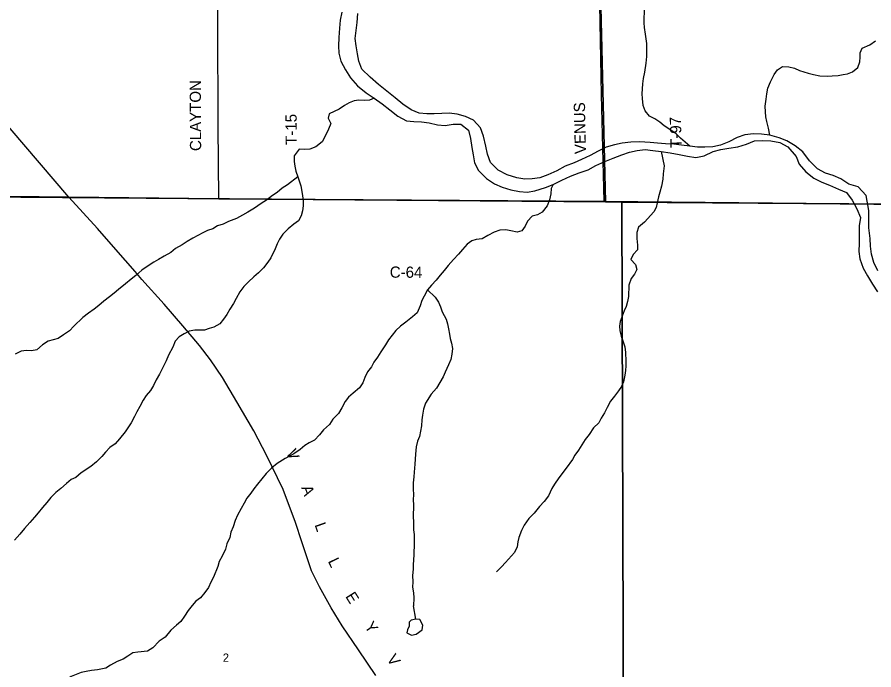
# Model space of a CAD drawing. Extents: x 1312308 to 1684953, y 460642 to 865172.
# Drawn here: x 1433853 to 1439573, y 606234 to 610594 of the extents above; entities that cross this region are included whole.
import ezdxf

# ---------------------------------------------------------------- set-up
doc = ezdxf.new("R2010")
doc.units = 0
for name, color, linetype in [('GM_X_County_Road', 7, 'Continuous'), ('GM_X_County_Road_Text', 7, 'Continuous'), ('GM_X_Minor_Lake', 7, 'Continuous'), ('GM_X_Minor_River', 7, 'Continuous'), ('GM_X_Section', 7, 'Continuous'), ('GM_X_Section_Text', 7, 'Continuous'), ('GM_X_Township', 7, 'Continuous'), ('GM_X_Township_Road', 7, 'Continuous'), ('GM_X_Township_Road_Text', 7, 'Continuous')]:
    doc.layers.add(name, color=color, linetype=linetype)

msp = doc.modelspace()

# ---------------------------------------------------------------- linework, layer by layer
at = {"layer": 'GM_X_County_Road'}
for points in [[(1434197.2, 609392.5), (1433321.1, 610416.1), (1432855.2, 610960.9), (1432519.8, 611370.7), (1432273.9, 611680.1), (1431928.4, 612099), (1431461.6, 612653.5), (1431109.8, 613075.1), (1430537.7, 613750.3), (1429745.8, 614732.5), (1429325.1, 615284.2), (1429124.3, 615518.8), (1428892, 615774.3), (1428690.9, 615972.9), (1428138.6, 616505.8), (1427967.9, 616667.8), (1427961, 616674.7)], [(1427248.1, 609464.9), (1427248.1, 609464.9), (1430057.8, 609437.8), (1434197.2, 609392.5)], [(1434197.2, 609392.5), (1435199.7, 609380.4), (1437771.4, 609361.5), (1440472, 609335.1), (1443062.5, 609310)], [(1436246.7, 606197), (1436132.6, 606368.7), (1436023, 606528.6), (1435948.4, 606647.6), (1435871.8, 606787.7), (1435819.1, 606895.2), (1435756.4, 607081.9), (1435709.1, 607224.4), (1435651.4, 607379.2), (1435629.5, 607438.2), (1435591.3, 607516.9), (1435519.6, 607663.1), (1435432.6, 607831.6), (1435319.8, 608023.6), (1435223.8, 608185.9), (1435144.7, 608305), (1435070.1, 608401.4), (1434958.9, 608532), (1434835.3, 608676.1), (1434685.7, 608841.3), (1434641.3, 608895.3), (1434511.5, 609042), (1434389.2, 609181.2), (1434197.2, 609392.5)]]:
    msp.add_lwpolyline(points, dxfattribs=at)
at = {"layer": 'GM_X_Minor_Lake'}
for points in [[(1436541.6, 606570.1), (1436515.6, 606572.6), (1436483.4, 606565.3), (1436471.1, 606553.6), (1436470.5, 606525.5), (1436458, 606501.8), (1436455.6, 606481.8), (1436485.3, 606465.1), (1436517.5, 606472.4)], [(1436517.5, 606472.4), (1436556.2, 606501.7), (1436560.9, 606533.6), (1436541.6, 606570.1)]]:
    msp.add_lwpolyline(points, dxfattribs=at)
at = {"layer": 'GM_X_Minor_River'}
for points in [[(1438343.3, 609732.7), (1438281.9, 609786.6), (1438252.4, 609815.3), (1438216.8, 609840), (1438173.2, 609866.9), (1438143.6, 609891.5), (1438110, 609914.2), (1438074.3, 609932.9), (1438046.9, 609967.5), (1438031.6, 610003.9), (1438028.6, 610050.1), (1438025.2, 610082.3), (1438030.6, 610148.4), (1438035.3, 610184.4), (1438044.2, 610226.4), (1438051.5, 610286.4), (1438056.4, 610330.5), (1438057.2, 610372.6), (1438056.1, 610416.8), (1438047.4, 610479.1), (1438042.3, 610525.3), (1438038.9, 610555.5), (1438041, 610657.8)], [(1436020.1, 610626.5), (1436008.9, 610572.6), (1436005.9, 610520.6), (1436000.6, 610458.6), (1435999.4, 610402.5), (1436000.4, 610352.4), (1436013.3, 610300), (1436044.2, 610241.2), (1436079.2, 610188.4), (1436126.2, 610135.3), (1436183.4, 610088), (1436236.8, 610052.7), (1436290.1, 610015.5), (1436341.4, 609974.3), (1436394.7, 609933.1), (1436452.2, 609901.8), (1436502.2, 609896.7), (1436552.3, 609893.6), (1436604.3, 609888.5), (1436660.1, 609875.3), (1436710.1, 609870.2), (1436764.5, 609879), (1436814.6, 609877.9), (1436865.9, 609838.8), (1436878.7, 609782.4), (1436887.6, 609724.1), (1436896.5, 609673.8), (1436905.5, 609621.5), (1436932.5, 609568.8), (1436985.5, 609515.6), (1437038.9, 609480.4), (1437090.5, 609457.2), (1437148.3, 609439.9), (1437206.2, 609428.7), (1437258.3, 609425.5), (1437308.6, 609434.5), (1437381.3, 609456.9), (1437431.8, 609475.9), (1437488.5, 609504.7), (1437547.2, 609531.5), (1437605.8, 609554.3), (1437664.4, 609575), (1437717.1, 609601.9), (1437775.8, 609630.7), (1437832.4, 609651.5), (1437891, 609674.3), (1437941.5, 609691.3), (1437991.8, 609702.2), (1438046.1, 609709), (1438096.1, 609703.9), (1438152.1, 609696.7), (1438212, 609687.4), (1438273.9, 609676), (1438327.8, 609664.9), (1438383.8, 609655.6), (1438440.2, 609668.4), (1438498.9, 609697.2), (1438551.3, 609710.1), (1438605.6, 609719), (1438664, 609727.7), (1438722.5, 609744.5), (1438775.1, 609767.4), (1438829.2, 609770.2), (1438885.3, 609767), (1438945.2, 609755.7), (1438998.8, 609726.5), (1439053.6, 609663.2), (1439074.6, 609612.7), (1439117.6, 609561.6), (1439172.9, 609518.4), (1439224.4, 609491.2), (1439276.2, 609472), (1439335.8, 609444.7), (1439389.5, 609423.5), (1439428.5, 609370.6), (1439459.3, 609313.8), (1439484.2, 609255.2)], [(1439540.1, 609241.9), (1439539.3, 609302.1), (1439521.3, 609402.6), (1439468.4, 609459.9), (1439406.6, 609477.2), (1439353.2, 609514.5), (1439301.5, 609535.6), (1439249.8, 609552.8), (1439196.2, 609580), (1439143.2, 609635.2), (1439098.3, 609694.3), (1439047, 609733.5), (1438991.6, 609766.7), (1438939.9, 609787.9), (1438878.1, 609805.2), (1438822.1, 609812.4), (1438770, 609813.6), (1438711.7, 609806.8), (1438661.2, 609789.9), (1438604.5, 609761.1), (1438547.9, 609738.2), (1438497.6, 609727.3), (1438445.4, 609724.4), (1438395.3, 609725.5), (1438343.3, 609732.7), (1438289.3, 609739.8), (1438237.3, 609745), (1438181.2, 609748.2), (1438129.1, 609751.3), (1438079.1, 609756.4), (1438007.1, 609762), (1437950.9, 609759.2), (1437892.6, 609752.4), (1437840.2, 609741.5), (1437785.8, 609724.7), (1437731.1, 609697.8), (1437678.4, 609668.9), (1437621.7, 609644.1), (1437571.1, 609621.1), (1437512.5, 609598.4), (1437455.7, 609567.5), (1437397, 609540.8), (1437342.5, 609519.9), (1437292.2, 609513), (1437242.1, 609512), (1437188.1, 609521.2), (1437124.4, 609540.6), (1437064.9, 609572), (1437013.8, 609623.2), (1436992.9, 609679.7), (1436982, 609732.1), (1436967.3, 609798.5), (1436946.4, 609855), (1436899.3, 609906.2), (1436845.7, 609929.3), (1436789.9, 609946.6), (1436737.9, 609951.7), (1436687.8, 609950.8), (1436637.6, 609947.9), (1436587.4, 609947), (1436537.4, 609952.1), (1436483.8, 609975.3), (1436428.4, 610012.5), (1436377.2, 610055.7), (1436321.9, 610099), (1436264.7, 610144.3), (1436209.6, 610193.6), (1436154.6, 610246.9), (1436133.6, 610299.4), (1436124.6, 610349.7), (1436115.7, 610402), (1436110.7, 610452.2), (1436115.8, 610504.2), (1436122.9, 610558.1), (1436128.2, 610618.1)], [(1438878.1, 609805.2), (1438868.9, 609852), (1438857.8, 609896.4), (1438852.4, 609928.6), (1438849.1, 609960.7), (1438847.9, 609998.9), (1438852.9, 610046.9), (1438857.6, 610080.9), (1438864.4, 610118.9), (1438883.3, 610162.7), (1438906.4, 610210.5), (1438929.1, 610242.1), (1438963.6, 610263.6), (1439005.7, 610262.8), (1439043.6, 610252.1), (1439077.4, 610237.4), (1439133.2, 610220.3), (1439169.1, 610211.6), (1439211.1, 610202.8), (1439263.2, 610199.9), (1439295.3, 610201.3), (1439333.5, 610204.6), (1439367.7, 610210), (1439397.9, 610215.4), (1439430.2, 610228.9), (1439466.9, 610258.3), (1439479.8, 610296.2), (1439482.4, 610326.2), (1439481, 610356.3), (1439495.6, 610386.2), (1439546.3, 610409.3), (1439584.9, 610436.7)], [(1436236.8, 610052.7), (1436205.1, 610039.7), (1436168.9, 610036.3), (1436134.9, 610039), (1436102.7, 610035.5), (1436070.4, 610022.1), (1436037.9, 610002.6), (1436003.3, 609979.2), (1435968.9, 609963.8), (1435936.5, 609948.3), (1435929.8, 609918.4), (1435947.2, 609883.9), (1435932.4, 609846.1), (1435907.2, 609794.4), (1435888.5, 609760.6), (1435847.7, 609727.3), (1435807.3, 609712), (1435773.1, 609710.6), (1435735.1, 609711.3), (1435702.1, 609667.8), (1435701.3, 609629.7), (1435706.7, 609599.5), (1435714, 609565.2), (1435727.3, 609526.9), (1435746.1, 609466.3), (1435753.4, 609430.1), (1435758.8, 609399.9), (1435762.2, 609369.7), (1435763.4, 609333.6), (1435758.7, 609299.6), (1435748, 609265.7), (1435731.3, 609233.9), (1435700.7, 609210.4), (1435662, 609181), (1435627.1, 609143.5), (1435604.4, 609109.8), (1435589.7, 609080), (1435575, 609046.2), (1435545.7, 608986.5), (1435527, 608956.8), (1435498.2, 608919.2), (1435463.4, 608885.8), (1435432.8, 608858.2), (1435398, 608824.8), (1435367.3, 608795.2), (1435340.5, 608759.6), (1435315.5, 608713.9), (1435296.7, 608680.2), (1435271.9, 608642.5), (1435253.1, 608608.8), (1435230.4, 608577.1), (1435205.7, 608545.4), (1435165.2, 608524.1), (1435134.9, 608514.7), (1435102.6, 608503.2), (1435072.5, 608503.8), (1435038.4, 608502.4), (1435002.1, 608497), (1434967.6, 608477.6), (1434935.2, 608458.2), (1434908.5, 608428.6), (1434891.6, 608388.7), (1434864.4, 608335.1), (1434847.7, 608299.3), (1434828.8, 608257.5), (1434803.7, 608209.8), (1434780.9, 608172.1), (1434762.1, 608134.3), (1434743.3, 608100.6), (1434714.5, 608067), (1434693.8, 608035.3), (1434670.9, 607993.6), (1434652.1, 607957.8), (1434637.4, 607926), (1434614.5, 607884.3), (1434573.2, 607824.9), (1434536.1, 607777.4), (1434507.3, 607743.8), (1434470.8, 607720.4), (1434442, 607688.9), (1434417.4, 607659.2), (1434382.5, 607623.8), (1434343.8, 607592.4), (1434280.7, 607549.4), (1434244, 607520), (1434213.7, 607506.5), (1434183, 607479), (1434144.2, 607445.6), (1434111.6, 607418.1), (1434076.8, 607384.7), (1434052, 607351), (1434021.2, 607317.5), (1433992.5, 607283.9), (1433967.8, 607254.3), (1433937, 607218.8), (1433902.1, 607179.3), (1433871.2, 607139.7), (1433834.3, 607100.3)], [(1438152.1, 609696.7), (1438171.8, 609600.1), (1438166.7, 609548), (1438164, 609511.9), (1438155, 609464), (1438144.1, 609424), (1438135.5, 609394.1), (1438126.6, 609354.2), (1438120, 609322.2), (1438103.3, 609292.4), (1438041.7, 609225.3), (1438000.9, 609190), (1437990.2, 609156), (1437989.4, 609115.9), (1437994.4, 609069.7), (1437995.8, 609039.6), (1437965.1, 609008.1), (1437950.4, 608974.2), (1437981.8, 608941.5), (1437991.1, 608907.3), (1437974.5, 608877.5), (1437951.8, 608847.8), (1437936.8, 608803.9), (1437935.3, 608727.7), (1437928.6, 608693.8), (1437919.9, 608661.8), (1437905.2, 608632), (1437892.5, 608596.1), (1437879.7, 608560.2), (1437875.1, 608530.2), (1437876.5, 608500.1), (1437885.7, 608463.8), (1437899, 608425.5), (1437910.3, 608391.2), (1437913.6, 608353), (1437916.4, 608296.8), (1437917.8, 608264.6), (1437915.1, 608232.6), (1437910.5, 608202.6), (1437901.6, 608158.6), (1437886.9, 608126.8), (1437868.2, 608097), (1437841.4, 608061.4), (1437814.6, 608027.8), (1437791.7, 607986.1), (1437774.9, 607950.3), (1437752.1, 607914.6), (1437735.5, 607884.8), (1437700.7, 607851.4), (1437671.7, 607805.8), (1437644.9, 607772.2), (1437624.1, 607736.4), (1437601.4, 607700.7), (1437576.6, 607669.1), (1437560, 607639.3), (1437518.7, 607581.9), (1437469.2, 607516.6), (1437440.3, 607475), (1437423.6, 607445.2), (1437400.6, 607397.5), (1437371.7, 607357.9), (1437340.9, 607324.4), (1437303.9, 607280.9), (1437269.1, 607245.5), (1437238.1, 607199.9), (1437221.3, 607164.1), (1437202.3, 607118.3), (1437195.7, 607088.3), (1437191, 607056.3), (1437174.2, 607018.5), (1437112.6, 606951.5), (1437086, 606921.9), (1437053.2, 606888.4)], [(1435727.3, 609526.9), (1435658, 609474), (1435621.4, 609450.6), (1435588.7, 609423.1), (1435558.2, 609401.6), (1435517.5, 609372.3), (1435482.9, 609348.8), (1435438.2, 609317.5), (1435393.5, 609290.3), (1435357, 609270.9), (1435318.4, 609249.5), (1435263.8, 609228.5), (1435227.4, 609211.1), (1435191, 609199.7), (1435158.5, 609180.3), (1435124.2, 609168.9), (1435091.8, 609153.4), (1435059.4, 609136), (1435024.9, 609116.5), (1434988.3, 609095.2), (1434953.8, 609073.7), (1434909.1, 609048.5), (1434878.5, 609022.9), (1434833.9, 608997.7), (1434797.3, 608974.3), (1434764.9, 608956.8), (1434728.3, 608933.4), (1434685.6, 608904.1), (1434644.7, 608868.8), (1434614.1, 608843.3), (1434575.3, 608811.9), (1434530.5, 608774.6), (1434499.9, 608751.1), (1434469.3, 608725.6), (1434432.6, 608696.2), (1434397.9, 608668.7), (1434367.3, 608643.2), (1434328.6, 608615.8), (1434292, 608588.4), (1434230.6, 608529.4), (1434201.9, 608497.8), (1434163.2, 608472.4), (1434126.6, 608447), (1434092.3, 608437.6), (1434060.1, 608430.2), (1434021.4, 608404.8), (1433984.7, 608371.4), (1433948.5, 608366.1), (1433914.4, 608366.7), (1433880.2, 608363.3), (1433839.6, 608342)], [(1437431.8, 609475.9), (1437418.5, 609449.5), (1437415.8, 609413.4), (1437407, 609373.4), (1437392.1, 609333.6), (1437359.2, 609292.1), (1437326.7, 609272.6), (1437290.4, 609265.3), (1437259.6, 609231.7), (1437244.9, 609197.9), (1437222.2, 609166.2), (1437191.9, 609156.8), (1437148, 609167.6), (1437116, 609172.2), (1437075.9, 609170.9), (1437037.5, 609157.6), (1436994.9, 609134.3), (1436958.3, 609112.9), (1436918.1, 609107.6), (1436887.9, 609100.2), (1436857.3, 609076.7), (1436826.5, 609041.1), (1436799.8, 609011.5), (1436767, 608974), (1436730, 608934.6), (1436703.3, 608901), (1436676.6, 608871.4), (1436649.8, 608837.8), (1436619.1, 608804.2), (1436592.3, 608772.6), (1436569.4, 608730.9), (1436554.8, 608701.1), (1436544, 608665.2), (1436523, 608619.4), (1436492.4, 608591.9), (1436447.5, 608556.6), (1436412.9, 608529.2), (1436382.2, 608501.6), (1436332.8, 608438.4), (1436312, 608404.6), (1436281, 608359.1), (1436258.2, 608323.4), (1436233.4, 608289.7), (1436218.8, 608257.9), (1436192, 608224.3), (1436175.2, 608186.5), (1436160.4, 608150.7), (1436137.6, 608117), (1436096.8, 608081.6), (1436066.2, 608056.1), (1436043.5, 608026.4), (1436020.6, 607984.7), (1435997.8, 607947), (1435960.9, 607909.6), (1435938.1, 607873.9), (1435897.2, 607836.5), (1435870.5, 607804.9), (1435837.7, 607769.4), (1435803.2, 607750), (1435772.7, 607732.5), (1435742.1, 607707), (1435699.4, 607677.7), (1435642.6, 607646.6), (1435589.8, 607613.5), (1435551, 607582.1), (1435516.2, 607546.7), (1435485.4, 607511.1), (1435458.6, 607475.5), (1435433.9, 607443.9), (1435413.2, 607414.2), (1435386.4, 607380.5), (1435367.7, 607346.8), (1435348.9, 607311), (1435324, 607267.3), (1435309.2, 607231.5), (1435294.3, 607189.7), (1435279.5, 607153.8), (1435272.8, 607117.8), (1435253.8, 607076.1), (1435243.1, 607040.1), (1435222.1, 606994.4), (1435201.3, 606958.7), (1435192.6, 606924.7), (1435163, 606853), (1435146.3, 606819.3), (1435129.5, 606783.5), (1435106.8, 606749.8), (1435078, 606716.2), (1435045.4, 606692.7), (1435020.7, 606663.1), (1434994, 606631.5), (1434969.2, 606593.8), (1434946.4, 606558.2), (1434915.8, 606532.6), (1434879, 606499.2), (1434841.9, 606451.8), (1434801.3, 606426.4), (1434758.2, 606381.1), (1434723.7, 606359.6), (1434659.4, 606352.8), (1434625.2, 606347.4)], [(1439484.2, 609255.2), (1439475, 609199.3), (1439473.8, 609141.2), (1439474.6, 609083.1), (1439473.5, 609029), (1439478.5, 608978.8), (1439501.2, 608916.2), (1439530.3, 608865.5), (1439563.2, 608810.7), (1439596.3, 608759.9)], [(1439599.2, 608900.1), (1439572.2, 608954.7), (1439557.3, 609011.2), (1439550.4, 609063.4), (1439547.5, 609115.6), (1439538.9, 609185.9), (1439540.1, 609241.9)], [(1436592.3, 608772.6), (1436643.5, 608723.5), (1436666.8, 608689), (1436680.3, 608658.6), (1436691.6, 608626.3), (1436716.7, 608575.7), (1436726.1, 608545.4), (1436733.4, 608511.2), (1436738.7, 608477), (1436744.1, 608446.8), (1436753.5, 608416.5), (1436758.8, 608380.3), (1436756, 608342.3), (1436747.3, 608306.3), (1436732.5, 608270.5), (1436711.5, 608222.7), (1436696.8, 608190.9), (1436673.9, 608153.2), (1436653.1, 608115.5), (1436616.2, 608076), (1436578.9, 608016.5), (1436566, 607974.6), (1436559.1, 607934.6), (1436554.5, 607904.6), (1436551.7, 607864.6), (1436538.2, 607792.6), (1436525.5, 607762.7), (1436516.7, 607724.8), (1436511.7, 607674.7), (1436508.3, 607608.6), (1436503.2, 607554.5), (1436500.5, 607522.5), (1436497.7, 607482.4), (1436496.9, 607442.3), (1436498.1, 607402.1), (1436497.5, 607372.1), (1436498.7, 607333.9), (1436497.1, 607255.7), (1436498.4, 607223.6), (1436499.3, 607169.4), (1436502.7, 607139.3), (1436504.1, 607109.1), (1436503.5, 607077.1), (1436502, 607004.9), (1436499.2, 606966.8), (1436496.6, 606936.8), (1436496, 606906.7), (1436493.1, 606864.6), (1436494.2, 606822.4), (1436493.5, 606786.3), (1436498.7, 606748.1), (1436502.1, 606716), (1436499, 606661.9)], [(1436515.6, 606572.6), (1436499, 606661.9)], [(1434625.2, 606347.4), (1434592.6, 606325.9), (1434560.1, 606306.5), (1434519.7, 606289.2), (1434477.1, 606265.9), (1434444.6, 606246.4), (1434390.2, 606235.4), (1434350, 606230.1), (1434313.7, 606222.8), (1434279.5, 606217.4), (1434212.8, 606190.5), (1434164, 606157.3), (1434105.3, 606132.3), (1434040.3, 606093.4), (1434001.8, 606074.1), (1433943.2, 606051.1)]]:
    msp.add_lwpolyline(points, dxfattribs=at)
at = {"layer": 'GM_X_Section'}
for points in [[(1437653.9, 614662.4), (1437782, 609359.8), (1432761, 609399.6), (1432499.1, 609405.2), (1432580.9, 614705.3)], [(1437653.9, 614662.4), (1443168.8, 614630.7), (1443044.1, 609319.5), (1437889.9, 609357.5), (1437782, 609359.8)], [(1432761, 609399.6), (1437782, 609359.8), (1437889.9, 609357.5), (1437907.9, 603579.3), (1432672, 603575.6)], [(1437889.9, 609357.5), (1443044.1, 609319.5), (1443050.1, 603939.8), (1443046.7, 603669.9), (1437907.9, 603579.3)]]:
    msp.add_lwpolyline(points, close=True, dxfattribs=at)
at = {"layer": 'GM_X_Township'}
for points in [[(1443487.4, 629689.1), (1443383.2, 625252.4), (1443279.1, 619936.6), (1443262.6, 619245.4), (1443164.3, 614625), (1443062.5, 609310), (1440472, 609335.1), (1437771.4, 609361.5), (1435199.7, 609380.4), (1434197.2, 609392.5), (1430057.8, 609437.8), (1427248.1, 609464.9), (1424759.1, 609498.2), (1422200.5, 609520.2), (1411036.3, 609617.7), (1410999.4, 609618.2), (1411017.8, 611981.1), (1411020.1, 612268.6), (1411090.2, 617032.9), (1411094.7, 617623.7), (1411153.4, 624951), (1411163.3, 625647.7), (1411180.4, 628296.4), (1411210.5, 633565.2)], [(1410955.4, 603991.6), (1410977, 606750.9), (1410982, 607392.1), (1410997.9, 609428.6), (1410999.4, 609618.2), (1411036.3, 609617.7), (1422200.5, 609520.2), (1424759.1, 609498.2), (1427248.1, 609464.9), (1430057.8, 609437.8), (1434197.2, 609392.5), (1435199.7, 609380.4), (1437771.4, 609361.5), (1440472, 609335.1), (1443062.5, 609310), (1445748.3, 609283.3), (1452218.2, 609194.8), (1453828.1, 609169), (1453803.6, 608986.7), (1453761.5, 603813.9)]]:
    msp.add_lwpolyline(points, dxfattribs=at)
at = {"layer": 'GM_X_Township_Road'}
for points in [[(1435199.7, 609380.4), (1435195.4, 609866.6), (1435189.5, 611248), (1435185.4, 611626.7), (1435177.2, 611678.5), (1435175.3, 611813.5), (1435164.1, 611930.3), (1435143.5, 612018.5), (1435131.6, 612084.2), (1435125.5, 612375), (1435139.5, 612960.1), (1435106.2, 614671.9)], [(1437771.4, 609361.5), (1437755.1, 610075.7), (1437743.6, 610676.9), (1437726.1, 611594.6), (1437707.1, 612286.1), (1437653.9, 614656.5)]]:
    msp.add_lwpolyline(points, dxfattribs=at)

# ---------------------------------------------------------------- texts
at = {"layer": 'GM_X_County_Road_Text'}
for s, rotation, p in [('C-64', 359.6558, (1436340.6, 608853.6)), ('V', 293.6135, (1435644.7, 607688.5)), ('A', 289.7264, (1435748.5, 607451.6)), ('L', 289.6527, (1435837.6, 607203.2)), ('L', 295.6125, (1435926.1, 606960.5)), ('E', 302.2654, (1436041.6, 606724.8)), ('Y', 304.3922, (1436168, 606524.9)), ('V', 304.4258, (1436317.3, 606306.9))]:
    msp.add_text(s, height=75, rotation=rotation, dxfattribs=at).set_placement(p)
at = {"layer": 'GM_X_Section_Text'}
msp.add_text('2', height=55.3, rotation=0, dxfattribs=at).set_placement((1435226.2, 606288))
at = {"layer": 'GM_X_Township_Road_Text'}
for s, rotation, p in [('CLAYTON', 90.2867, (1435081.7, 609699.7)), ('VENUS', 91.2365, (1437651.2, 609680.3)), ('T-15', 90.3383, (1435720.2, 609741.1)), ('T-97', 91.4143, (1438289.9, 609722.1))]:
    msp.add_text(s, height=75, rotation=rotation, dxfattribs=at).set_placement(p)

doc.saveas('drawing.dxf')
